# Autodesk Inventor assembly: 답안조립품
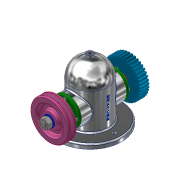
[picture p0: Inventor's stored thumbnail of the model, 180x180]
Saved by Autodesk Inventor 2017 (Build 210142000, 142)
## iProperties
Created: 2019-11
Part Number: 답안조립품
Document SubType Name: Assembly
Designer: 1-06-lg
Author: 1-06-lg
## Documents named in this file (14)
- C:\Users\1-06-lg\Desktop\491104V1006\답안조립품.iam
- C:\Users\1-06-lg\Desktop\491104V1006\본체.ipt
- C:\Users\1-06-lg\Desktop\491104V1006\V-벨트풀리.ipt
- V-벨트풀리.ipt
- C:\Users\1-06-lg\Desktop\491104V1006\너트 M12x1.25.ipt
- C:\Users\1-06-lg\Desktop\491104V1006\베어링 6203.ipt
- C:\Users\1-06-lg\Desktop\491104V1006\볼트 M4.ipt
- C:\Users\1-06-lg\Desktop\491104V1006\부시.ipt
- C:\Users\1-06-lg\Desktop\491104V1006\스퍼기어.ipt
- C:\Users\1-06-lg\Desktop\491104V1006\오일 실 26 38 8.ipt
- C:\Users\1-06-lg\Desktop\491104V1006\와셔 12x24.ipt
- C:\Users\1-06-lg\Desktop\491104V1006\축.ipt
- C:\Users\1-06-lg\Desktop\491104V1006\커버.ipt
- C:\Users\1-06-lg\Desktop\491104V1006\키 5x5x12.ipt
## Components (1 placed, 1 different names)
1. V-벨트풀리:1 — Angle:1, Insert:11, Insert:12
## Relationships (3: Insert 2, Angle 1)
- Angle:1: V-벨트풀리:1
- Insert:11: V-벨트풀리:1
- Insert:12: V-벨트풀리:1
